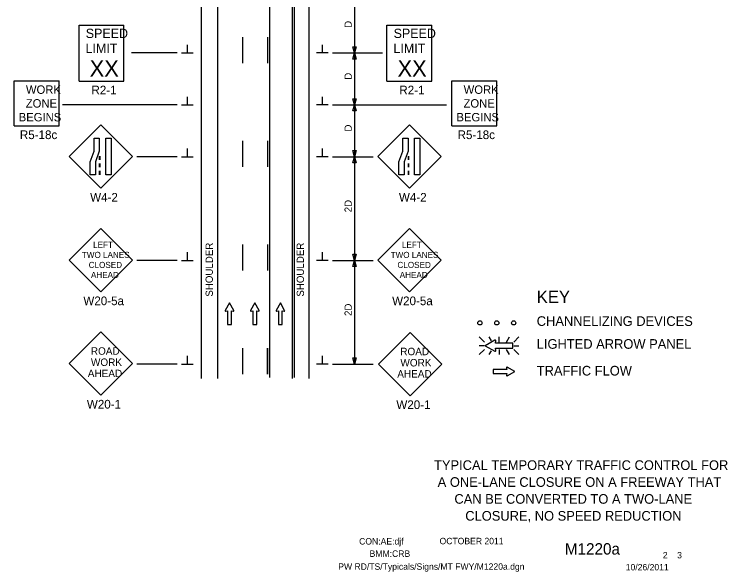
# Model space of a CAD drawing. Extents: x 16782 to 19504, y 6935 to 8243.
# Drawn here: x 17787 to 18475, y 7218 to 7756 of the extents above; entities that cross this region are included whole.
import ezdxf

# ---------------------------------------------------------------- set-up
doc = ezdxf.new("R2010")
doc.units = 0
for name, color, linetype in [('ALI_LEGAL_EX', 7, 'Continuous'), ('BORDER', 7, 'Continuous'), ('BORDER_SIGNAL_WO', 7, 'Continuous'), ('MT_SCRATCH_LEVEL_E', 7, 'Continuous'), ('PAVT_EDGE_EX', 7, 'Continuous'), ('TRAFFIC_SIGNS_PR', 7, 'Continuous'), ('TYPICAL_TEXT_DIMEN_EX', 7, 'Continuous'), ('TYPICAL_TEXT_DIMEN_PR', 7, 'Continuous')]:
    doc.layers.add(name, color=color, linetype=linetype)

msp = doc.modelspace()

# ---------------------------------------------------------------- linework, layer by layer
at = {"layer": 'ALI_LEGAL_EX'}
for p, q in [((18033.11, 8234.45), (18033.11, 7405.27)), ((18057.11, 8234.45), (18057.11, 7405.27)), ((18057.11, 8234.45), (18057.11, 7405.27))]:
    msp.add_line(p, q, dxfattribs=at)
for points in [[(18007.13, 7733.65), (18007.13, 7708.65)], [(18031.13, 7733.65), (18031.13, 7708.65)], [(18007.13, 7633.65), (18007.13, 7608.65)], [(18031.13, 7633.65), (18031.13, 7608.65)], [(18007.13, 7533.65), (18007.13, 7508.65)], [(18031.13, 7533.65), (18031.13, 7508.65)], [(18007.13, 7433.65), (18007.13, 7408.65)], [(18031.13, 7408.65), (18031.13, 7433.65)], [(18031.13, 7433.65), (18031.13, 7408.65)]]:
    msp.add_lwpolyline(points, dxfattribs=at)
at = {"layer": 'MT_SCRATCH_LEVEL_E'}
for p, q in [((17994.57, 7477.28), (17990.46, 7470.04)), ((17998.71, 7470.04), (17994.57, 7477.28)), ((18019.1, 7477.28), (18014.98, 7470.04)), ((18023.24, 7470.04), (18019.1, 7477.28)), ((18043.65, 7477.28), (18039.54, 7470.04)), ((18047.8, 7470.04), (18043.65, 7477.28)), ((17990.94, 7469.36), (17992.71, 7469.68)), ((17992.71, 7469.68), (17992.71, 7456.42)), ((17996.46, 7456.42), (17996.46, 7469.68)), ((17996.46, 7469.68), (17998.23, 7469.36)), ((18015.47, 7469.36), (18017.24, 7469.68)), ((18017.24, 7469.68), (18017.24, 7456.42)), ((18020.99, 7456.42), (18020.99, 7469.68)), ((18020.99, 7469.68), (18022.76, 7469.36)), ((18040.03, 7469.36), (18041.8, 7469.68)), ((18041.8, 7469.68), (18041.8, 7456.42)), ((18045.54, 7456.42), (18045.54, 7469.68)), ((18045.54, 7469.68), (18047.32, 7469.36)), ((17992.71, 7456.42), (17996.46, 7456.42)), ((18017.24, 7456.42), (18020.99, 7456.42)), ((18041.8, 7456.42), (18045.54, 7456.42)), ((18269.84, 7411.16), (18262.6, 7415.27)), ((18262.23, 7413.01), (18248.97, 7413.01)), ((18248.97, 7413.01), (18248.97, 7409.27)), ((18248.97, 7409.27), (18262.23, 7409.27)), ((18261.91, 7414.79), (18262.23, 7413.01)), ((18262.23, 7409.27), (18261.91, 7407.49)), ((18262.6, 7407.01), (18269.84, 7411.16))]:
    msp.add_line(p, q, dxfattribs=at)
for centre, start, end in [((17990.86, 7469.82), 150.42484, 279.96381), ((17998.3, 7469.82), 260.03619, 29.77312), ((18015.39, 7469.82), 150.42484, 279.96381), ((18022.83, 7469.82), 260.03619, 29.77312), ((18039.95, 7469.82), 150.42484, 279.96381), ((18047.39, 7469.82), 260.03619, 29.77312), ((18262.37, 7414.86), 60.42484, 189.96381), ((18262.37, 7407.42), 170.03619, 299.77312)]:
    msp.add_arc(centre, 0.463, start, end, dxfattribs=at)
at = {"layer": 'PAVT_EDGE_EX'}
for p, q in [((17967.13, 8183.26), (17967.13, 7404.46)), ((17983.13, 8183.26), (17983.13, 7404.46)), ((18055.13, 8183.26), (18055.13, 7404.46)), ((18071.13, 8183.26), (18071.13, 7404.46))]:
    msp.add_line(p, q, dxfattribs=at)
at = {"layer": 'TRAFFIC_SIGNS_PR'}
for p, q in [((17849.38, 7745.33), (17892.58, 7745.33)), ((17849.38, 7691.33), (17849.38, 7745.33)), ((17892.58, 7691.33), (17892.58, 7745.33)), ((18146.48, 7745.33), (18189.68, 7745.33)), ((18146.48, 7691.33), (18146.48, 7745.33)), ((18189.68, 7691.33), (18189.68, 7745.33)), ((17786.9, 7648.19), (17786.9, 7691.39)), ((17786.9, 7691.39), (17830.1, 7691.39)), ((17830.1, 7648.19), (17830.1, 7691.39)), ((17849.38, 7691.33), (17892.58, 7691.33)), ((18146.48, 7691.33), (18189.68, 7691.33)), ((18209.29, 7648.19), (18209.29, 7691.39)), ((18209.29, 7691.39), (18252.49, 7691.39)), ((18252.49, 7648.19), (18252.49, 7691.39)), ((17870.29, 7648.96), (17839.75, 7618.41)), ((17900.84, 7618.41), (17870.29, 7648.96)), ((18168.26, 7648.96), (18137.71, 7618.41)), ((18198.81, 7618.41), (18168.26, 7648.96)), ((17786.9, 7648.19), (17830.1, 7648.19)), ((18209.29, 7648.19), (18252.49, 7648.19)), ((17839.75, 7618.41), (17870.29, 7587.87)), ((17868.89, 7618.97), (17868.89, 7615.37)), ((17869.34, 7618.97), (17869.34, 7615.37)), ((17870.29, 7587.87), (17900.84, 7618.41)), ((18137.71, 7618.41), (18168.26, 7587.87)), ((18166.86, 7618.97), (18166.86, 7615.37)), ((18167.31, 7618.97), (18167.31, 7615.37)), ((18168.26, 7587.87), (18198.81, 7618.41)), ((17868.89, 7611.77), (17868.89, 7608.17)), ((17869.34, 7611.77), (17869.34, 7608.17)), ((18166.86, 7611.77), (18166.86, 7608.17)), ((18167.31, 7611.77), (18167.31, 7608.17)), ((17868.89, 7604.57), (17868.89, 7600.97)), ((17869.34, 7604.57), (17869.34, 7600.97)), ((18166.86, 7604.57), (18166.86, 7600.97)), ((18167.31, 7604.57), (18167.31, 7600.97)), ((17870.29, 7549.11), (17839.75, 7518.56)), ((17900.84, 7518.56), (17870.29, 7549.11)), ((18168.26, 7549.11), (18137.71, 7518.56)), ((18198.81, 7518.56), (18168.26, 7549.11)), ((17839.75, 7518.56), (17870.29, 7488.01)), ((17870.29, 7488.01), (17900.84, 7518.56)), ((18137.71, 7518.56), (18168.26, 7488.01)), ((18168.26, 7488.01), (18198.81, 7518.56)), ((17870.28, 7449.42), (17839.74, 7418.87)), ((17900.83, 7418.87), (17870.28, 7449.42)), ((18168.91, 7448.94), (18138.37, 7418.4)), ((18199.46, 7418.4), (18168.91, 7448.94)), ((18235.65, 7444.54), (18240.58, 7439.61)), ((18247.41, 7440.72), (18245.2, 7444.55)), ((18254.73, 7439.61), (18254.73, 7444.55)), ((18261.97, 7439.61), (18264.82, 7444.55)), ((18268.88, 7439.61), (18273.82, 7444.55)), ((18240.58, 7436.06), (18235.65, 7436.06)), ((18268.88, 7436.06), (18273.82, 7436.06)), ((18235.65, 7427.57), (18240.58, 7432.5)), ((18245.16, 7427.57), (18247.27, 7431.23)), ((18254.73, 7432.5), (18254.73, 7427.57)), ((18264.86, 7427.57), (18262.01, 7432.5)), ((18268.88, 7432.5), (18273.82, 7427.56)), ((17839.74, 7418.87), (17870.28, 7388.32)), ((17870.28, 7388.32), (17900.83, 7418.87)), ((18138.37, 7418.4), (18168.91, 7387.85)), ((18168.91, 7387.85), (18199.46, 7418.4))]:
    msp.add_line(p, q, dxfattribs=at)
for points in [[(17868.89, 7636.12), (17868.89, 7623.54), (17865.13, 7613.54), (17865.13, 7600.97), (17860.07, 7600.97), (17860.07, 7613.54), (17863.84, 7623.54), (17863.84, 7636.12)], [(17880.29, 7636.12), (17880.29, 7600.97), (17875.24, 7600.97), (17875.24, 7636.12)], [(18166.86, 7636.12), (18166.86, 7623.54), (18163.09, 7613.54), (18163.09, 7600.97), (18158.04, 7600.97), (18158.04, 7613.54), (18161.8, 7623.54), (18161.8, 7636.12)], [(18178.26, 7636.12), (18178.26, 7600.97), (18173.2, 7600.97), (18173.2, 7636.12)]]:
    msp.add_lwpolyline(points, close=True, dxfattribs=at)
for points in [[(18250.66, 7441.33), (18241.37, 7436.06), (18250.66, 7430.73)], [(18251.53, 7431.36), (18251.13, 7433.63), (18268.15, 7433.63), (18268.15, 7438.43), (18251.13, 7438.43), (18251.54, 7440.71)]]:
    msp.add_lwpolyline(points, dxfattribs=at)
for centre in [(18236.21, 7458.09), (18252.51, 7458.09), (18268.81, 7458.09)]:
    msp.add_circle(centre, 2, dxfattribs=at)
for centre, radius, start, end in [((18250.95, 7440.81), 0.598, 350.73078, 118.89165), ((18250.95, 7431.26), 0.597, 241.48329, 9.95933)]:
    msp.add_arc(centre, radius, start, end, dxfattribs=at)
at = {"layer": 'TYPICAL_TEXT_DIMEN_PR'}
for p, q in [((18115.13, 7768.36), (18115.13, 7718.36)), ((17954, 7718.36), (17954, 7726.15)), ((18084.25, 7718.36), (18084.25, 7726.15)), ((17944.13, 7718.36), (17900.06, 7718.36)), ((17948.38, 7718.36), (17959.63, 7718.36)), ((18089.88, 7718.36), (18078.63, 7718.36)), ((18094.13, 7718.36), (18142.36, 7718.36)), ((18115.13, 7718.36), (18113.56, 7724.23)), ((18113.56, 7724.23), (18115.13, 7724.23)), ((18113.56, 7712.5), (18115.13, 7718.36)), ((18115.13, 7724.23), (18116.7, 7724.23)), ((18116.7, 7724.23), (18115.13, 7718.36)), ((18115.13, 7718.36), (18116.7, 7712.5)), ((18115.13, 7718.36), (18115.13, 7668.36)), ((18115.13, 7712.5), (18113.56, 7712.5)), ((18116.7, 7712.5), (18115.13, 7712.5)), ((17954, 7668.36), (17954, 7676.15)), ((18084.25, 7668.36), (18084.25, 7676.15)), ((18115.13, 7668.36), (18113.56, 7674.23)), ((18113.56, 7674.23), (18115.13, 7674.23)), ((18115.13, 7674.23), (18116.7, 7674.23)), ((18116.7, 7674.23), (18115.13, 7668.36)), ((17944.13, 7668.36), (17833.33, 7668.36)), ((17948.38, 7668.36), (17959.63, 7668.36)), ((18089.88, 7668.36), (18078.63, 7668.36)), ((18094.13, 7668.36), (18203.88, 7668.36)), ((18113.56, 7662.5), (18115.13, 7668.36)), ((18115.13, 7668.36), (18116.7, 7662.5)), ((18115.13, 7668.36), (18115.13, 7618.36)), ((18115.13, 7662.5), (18113.56, 7662.5)), ((18116.7, 7662.5), (18115.13, 7662.5)), ((17954, 7618.36), (17954, 7626.15)), ((18084.25, 7618.36), (18084.25, 7626.15)), ((18115.13, 7618.36), (18113.56, 7624.23)), ((18113.56, 7624.23), (18115.13, 7624.23)), ((18115.13, 7624.23), (18116.7, 7624.23)), ((18116.7, 7624.23), (18115.13, 7618.36)), ((17944.13, 7618.36), (17905.13, 7618.36)), ((17948.38, 7618.36), (17959.63, 7618.36)), ((18089.88, 7618.36), (18078.63, 7618.36)), ((18094.13, 7618.36), (18133.13, 7618.36)), ((18113.56, 7612.5), (18115.13, 7618.36)), ((18115.13, 7618.36), (18115.13, 7518.36)), ((18115.13, 7618.36), (18116.7, 7612.5)), ((18115.13, 7612.5), (18113.56, 7612.5)), ((18116.7, 7612.5), (18115.13, 7612.5)), ((17954, 7518.36), (17954, 7526.15)), ((18084.25, 7518.36), (18084.25, 7526.15)), ((17944.13, 7518.36), (17905.13, 7518.36)), ((17948.38, 7518.36), (17959.63, 7518.36)), ((18089.88, 7518.36), (18078.63, 7518.36)), ((18094.13, 7518.36), (18133.13, 7518.36)), ((18115.13, 7518.36), (18113.56, 7524.23)), ((18113.56, 7524.23), (18115.13, 7524.23)), ((18113.56, 7512.5), (18115.13, 7518.36)), ((18115.13, 7524.23), (18116.7, 7524.23)), ((18116.7, 7524.23), (18115.13, 7518.36)), ((18115.13, 7518.36), (18115.13, 7418.36)), ((18115.13, 7518.36), (18116.7, 7512.5)), ((18115.13, 7512.5), (18113.56, 7512.5)), ((18116.7, 7512.5), (18115.13, 7512.5)), ((17954, 7418.36), (17954, 7426.15)), ((18084.25, 7418.36), (18084.25, 7426.15)), ((18115.13, 7418.36), (18113.56, 7424.23)), ((18113.56, 7424.23), (18115.13, 7424.23)), ((18115.13, 7424.23), (18116.7, 7424.23)), ((18116.7, 7424.23), (18115.13, 7418.36)), ((17944.13, 7418.36), (17905.13, 7418.36)), ((17948.38, 7418.36), (17959.63, 7418.36)), ((18089.88, 7418.36), (18078.63, 7418.36)), ((18094.13, 7418.36), (18133.13, 7418.36))]:
    msp.add_line(p, q, dxfattribs=at)

# ---------------------------------------------------------------- texts
at = {"layer": 'BORDER'}
for s, p in [('TYPICAL TEMPORARY TRAFFIC CONTROL FOR', (18191.96, 7316.24)), ('A ONE-LANE CLOSURE ON A FREEWAY THAT', (18195.47, 7299.94)), ('CAN BE CONVERTED TO A TWO-LANE ', (18211.62, 7283.64)), ('CLOSURE, NO SPEED REDUCTION ', (18222.1, 7267.34))]:
    msp.add_text(s, height=9.3, dxfattribs=at).set_placement(p)
at = {"layer": 'BORDER_SIGNAL_WO'}
for s, height, p in [('CON:AE:djf  ', 6.2, (18119.69, 7244.31)), ('    OCTOBER 2011    ', 6.2, (18188.08, 7244.59)), ('    M1220a   ', 11, (18301.86, 7234.63)), ('BMM:CRB   ', 6.2, (18129.81, 7232.42)), (' 2    3 ', 6.2, (18410.45, 7230.95)), ('PW RD/TS/Typicals/Signs/MT FWY/M1220a.dgn      ', 6.2, (18099.55, 7219.96)), ('10/26/2011    ', 6.2, (18376.93, 7219.38))]:
    msp.add_text(s, height=height, dxfattribs=at).set_placement(p)
at = {"layer": 'TRAFFIC_SIGNS_PR'}
for s, height, p in [('SPEED', 9, (17855.87, 7732.8)), ('SPEED', 9, (18152.96, 7732.8)), ('LIMIT', 9, (17855.69, 7718.4)), ('LIMIT', 9, (18152.78, 7718.4)), ('XX', 15.785, (17859.64, 7695.56)), ('XX', 15.785, (18156.73, 7695.56)), ('WORK', 8.119, (17798.15, 7678.98)), ('R2-1', 8.37, (17861.39, 7678.46)), ('R2-1', 8.37, (18158.49, 7678.46)), ('WORK', 8.119, (18220.54, 7678.98)), ('ZONE', 8.119, (17798.01, 7665.69)), ('ZONE', 8.119, (18220.41, 7665.69)), ('BEGINS', 8.119, (17791.18, 7652.4)), ('BEGINS', 8.119, (18213.58, 7652.4)), ('R5-18c', 8.37, (17792.31, 7635.32)), ('R5-18c', 8.37, (18214.7, 7635.32)), ('W4-2', 8.37, (17860.12, 7575)), ('W4-2', 8.37, (18158.09, 7575)), ('LEFT', 5.85, (17863.02, 7530.41)), ('LEFT', 5.85, (18160.99, 7530.41)), ('TWO LANES', 5.85, (17852.14, 7520.74)), ('TWO LANES', 5.85, (18150.1, 7520.74)), ('CLOSED', 5.85, (17858.72, 7511.06)), ('CLOSED', 5.85, (18156.68, 7511.06)), ('AHEAD', 5.85, (17860.91, 7501.39)), ('AHEAD', 5.85, (18158.87, 7501.39)), ('W20-5a', 8.37, (17853.58, 7475.14)), ('W20-5a', 8.37, (18151.54, 7475.14)), ('ROAD', 7.2, (17860.77, 7427.35)), ('ROAD', 7.2, (18159.4, 7426.88)), ('WORK', 7.2, (17860.89, 7416.55)), ('WORK', 7.2, (18159.52, 7416.07)), ('AHEAD', 7.2, (17857.86, 7405.75)), ('AHEAD', 7.2, (18156.49, 7405.28)), ('W20-1', 8.37, (17856.97, 7375.45)), ('W20-1', 8.37, (18155.6, 7374.98))]:
    msp.add_text(s, height=height, dxfattribs=at).set_placement(p)
at = {"layer": 'TYPICAL_TEXT_DIMEN_EX'}
for s, height, p in [('KEY', 12, (18291.05, 7477.2)), ('CHANNELIZING DEVICES', 9.3, (18291.05, 7455.15)), ('LIGHTED ARROW PANEL', 9.3, (18291.05, 7433.1)), ('TRAFFIC FLOW', 9.3, (18291.05, 7407.3))]:
    msp.add_text(s, height=height, dxfattribs=at).set_placement(p)
at = {"layer": 'TYPICAL_TEXT_DIMEN_PR'}
for s, p in [('D', (18112.57, 7742.58)), ('D', (18112.57, 7692.58)), ('D', (18112.57, 7642.58)), ('2D', (18112.57, 7564.73)), ('SHOULDER', (17978.51, 7483.39)), ('SHOULDER', (18066.41, 7483.39)), ('2D', (18112.57, 7464.73))]:
    msp.add_text(s, height=7, rotation=90, dxfattribs=at).set_placement(p)

doc.saveas('drawing.dxf')
